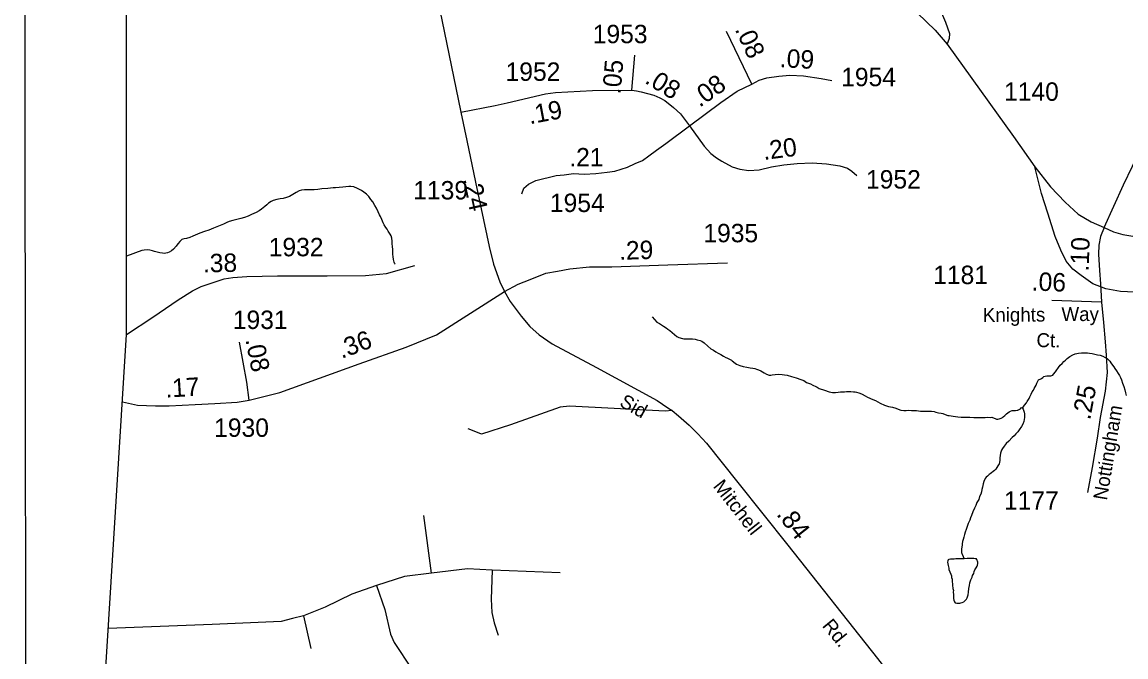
# Model space of a CAD drawing. Extents: x 2126262 to 2293712, y 749403 to 919119.
# Drawn here: x 2133630 to 2141122, y 833147 to 837456 of the extents above; entities that cross this region are included whole.
import ezdxf

# ---------------------------------------------------------------- set-up
doc = ezdxf.new("R2010")
doc.units = 0
for name, color, linetype in [('Exist Boundary Political CountyLine', 7, 'Continuous'), ('Exist Hydrographic Creek Single Shore', 7, 'Continuous'), ('Exist Hydrographic Misc Water Feature', 7, 'Continuous'), ('Exist Road Non-System Type 51', 7, 'Continuous'), ('Exist Road Secondary Mileage Hundredths English Label', 7, 'Continuous'), ('Exist Road Secondary Type 51 Attributed', 7, 'Continuous'), ('Exist Road Secondary Type 51 Label', 7, 'Continuous'), ('Exist Road Secondary Type 51 Number Label', 7, 'Continuous'), ('Map Preparation Inset Cut Line', 7, 'Continuous')]:
    doc.layers.add(name, color=color, linetype=linetype)

msp = doc.modelspace()

# ---------------------------------------------------------------- linework, layer by layer
at = {"layer": 'Exist Boundary Political CountyLine'}
msp.add_lwpolyline([(2133839.4, 827270.1), (2134339.4, 835334.3), (2134341.8, 841203.1), (2134508, 848637.7), (2140998.3, 864497.6)], dxfattribs=at)
at = {"layer": 'Exist Hydrographic Creek Single Shore'}
msp.add_lwpolyline([(2140527.4, 835028.2), (2140533.2, 835029.3), (2140539.3, 835032.5), (2140547.7, 835037.3), (2140557.6, 835044.7), (2140565.6, 835050), (2140573.1, 835052.5), (2140585.4, 835054.7), (2140599.2, 835055.1), (2140611.5, 835054.8), (2140619.9, 835057.2), (2140625.8, 835059.5), (2140631, 835065.3), (2140643.1, 835081.3), (2140648.6, 835089.4), (2140665, 835111.2), (2140676.1, 835126.6), (2140688.4, 835139.4), (2140700.7, 835151.7), (2140710.9, 835160.3), (2140723.9, 835171.7), (2140742.1, 835186), (2140760.4, 835197), (2140777.8, 835204.1), (2140799.5, 835209.4), (2140819.6, 835210.8), (2140843.8, 835210.8), (2140860.4, 835210.7), (2140875.6, 835209.6), (2140893.6, 835205.6), (2140910.5, 835202.3), (2140927.9, 835197.6), (2140946.1, 835194.1), (2140965.8, 835187.8), (2140982, 835180.1), (2140994.5, 835171.7), (2141004.2, 835162.6), (2141012.2, 835154.1), (2141020.4, 835142.6), (2141030.6, 835128.1), (2141038.6, 835116.7), (2141046.4, 835105.1), (2141056.9, 835089.2), (2141068.8, 835070.8), (2141077.8, 835056.1), (2141085.4, 835042.7), (2141091.1, 835026.8), (2141099.5, 835005.3), (2141107.7, 834983), (2141113.9, 834961), (2141120, 834939.3), (2141124.1, 834921.2)], dxfattribs=at)
at = {"layer": 'Exist Hydrographic Misc Water Feature'}
for points in [[(2136162.1, 835811.9), (2136160.2, 835815.8), (2136156.1, 835827.4), (2136151.8, 835844.3), (2136149.8, 835865.3), (2136147.5, 835879.4), (2136147.1, 835893.2), (2136145.5, 835913.8), (2136145, 835929.3), (2136142.8, 835953.2), (2136143, 835969.8), (2136140.7, 835989.6), (2136134.4, 836005.9), (2136128.2, 836017.4), (2136115.9, 836037.5), (2136108.1, 836049.3), (2136099.9, 836061.9), (2136088, 836079.1), (2136081.9, 836093), (2136075.7, 836104.9), (2136071.4, 836114.9), (2136063.4, 836135.5), (2136055.4, 836148.6), (2136047, 836166.9), (2136035.1, 836192.6), (2136024.5, 836210.9), (2136010.3, 836234.9), (2135998.4, 836252.5), (2135984.1, 836270.9), (2135968.1, 836288.3), (2135950, 836301.6), (2135933.4, 836311.8), (2135907.6, 836327.1), (2135881.6, 836337.5), (2135861.9, 836338.9), (2135847.9, 836339), (2135827.6, 836337.2), (2135807.7, 836335), (2135781.7, 836332.4), (2135758.1, 836330.3), (2135741.9, 836329.9), (2135705.8, 836325.6), (2135663.8, 836323.5), (2135638, 836318.9), (2135613.8, 836316.8), (2135555.9, 836316.7), (2135546.3, 836316.5), (2135527.6, 836314.5), (2135510.4, 836310.2), (2135489.9, 836299.9), (2135468.4, 836285.7), (2135444.4, 836271.1), (2135425.9, 836264.9), (2135402.3, 836258.8), (2135382.7, 836255.2), (2135358.5, 836250.8), (2135334.9, 836244.6), (2135320.7, 836238.6), (2135303.1, 836226.3), (2135290.6, 836216), (2135277.3, 836204.2), (2135255.5, 836185.6), (2135239.3, 836175.5), (2135219.4, 836163.5), (2135203.7, 836155.7), (2135187.9, 836149.2), (2135164.1, 836139), (2135140.1, 836130.5), (2135115.9, 836122.8), (2135087.8, 836115.3), (2135060.3, 836108.5), (2135036.1, 836101.6), (2135020.3, 836095.5), (2134996.6, 836085.3), (2134964.4, 836071.1), (2134930.7, 836057.1), (2134898.7, 836044.5), (2134868.6, 836033.6), (2134837.2, 836022.2), (2134789.2, 836001.8), (2134769.4, 835993.9), (2134747.4, 835987.9), (2134731.2, 835985), (2134721.2, 835983.3), (2134715.2, 835981), (2134709.5, 835974.5), (2134701.9, 835966.8), (2134689.8, 835952.8), (2134681.6, 835942.6), (2134676.1, 835934.2), (2134658.2, 835914.1), (2134643.9, 835902.1), (2134628.7, 835894.3), (2134616.4, 835890.5), (2134594.4, 835886.1), (2134584.4, 835886.4), (2134566.1, 835889.9), (2134547.9, 835894.4), (2134528.4, 835899.7), (2134514.5, 835903.4)], [(2134514.5, 835903.4), (2134498.1, 835906.8), (2134480.2, 835909), (2134458.1, 835906.7), (2134442.1, 835904.7), (2134339.6, 835867.6)], [(2137906.6, 835455.3), (2137938.8, 835419.2), (2137956.9, 835410), (2137969, 835401.6), (2137983.1, 835392.2), (2138001.2, 835380.1), (2138013.5, 835371.8), (2138025.4, 835362.7), (2138043.4, 835348.1), (2138057.6, 835336.3), (2138073.8, 835322.9), (2138087.9, 835314.6), (2138111.7, 835309), (2138122, 835307.1), (2138143.7, 835305), (2138165.8, 835305.3), (2138180, 835305.2), (2138198, 835304.1), (2138211.8, 835299.6), (2138231.7, 835294.1), (2138244.2, 835289.8), (2138260, 835278.1), (2138284.4, 835256.1), (2138304.5, 835238.5), (2138322.3, 835228.5), (2138338.5, 835216.7), (2138354.7, 835209), (2138372.7, 835199.3), (2138391, 835189.3), (2138406.8, 835179.2), (2138412.7, 835177.4), (2138445.1, 835162), (2138449, 835157.8), (2138469.1, 835140.1), (2138479.2, 835134.1), (2138501.3, 835124.7), (2138523.7, 835118.5), (2138549.1, 835113), (2138571.4, 835109.2), (2138589.3, 835107.3), (2138603.4, 835105.6), (2138615.5, 835100.9), (2138627.6, 835095), (2138643.8, 835089.7), (2138655.5, 835081.5), (2138667.4, 835076), (2138683.6, 835065.8), (2138699.6, 835059.8), (2138711.9, 835060.4), (2138722.1, 835062.1), (2138741.6, 835064.8), (2138763.6, 835066.7), (2138788, 835064.7), (2138805.8, 835062.8), (2138821.8, 835059.1), (2138851.9, 835050.9), (2138883.9, 835041.2), (2138915.9, 835029.9), (2138936.4, 835022.3), (2138953.9, 835010.3), (2138980.3, 835000.6), (2138996.3, 834992.1), (2139016.6, 834983), (2139026.6, 834977), (2139040.6, 834969.2), (2139076.7, 834956.9), (2139108.5, 834945.6), (2139130.8, 834941.8), (2139150.9, 834942.4), (2139169.2, 834944.5), (2139184.7, 834946.6), (2139198.7, 834946.1), (2139208.5, 834947), (2139212.8, 834946.8), (2139224.7, 834949.1), (2139242.4, 834948.8), (2139254.9, 834949.4), (2139272.7, 834947.1), (2139284.8, 834945.2), (2139292.6, 834943.6), (2139308.4, 834939.2), (2139326.6, 834933.6), (2139330.7, 834929.8), (2139352.9, 834919.9), (2139368.9, 834909.8), (2139405.2, 834894.6), (2139421.2, 834886.9), (2139455, 834870.4), (2139483.3, 834856.7), (2139511.6, 834847.2), (2139537.4, 834841.7), (2139559.4, 834835.5), (2139575.4, 834829.5), (2139593.6, 834821.8), (2139615.3, 834820.5), (2139631.5, 834820.1), (2139643.4, 834820.8), (2139665.6, 834820.2), (2139691.6, 834818.8), (2139699.6, 834818.8)], [(2140418.1, 834840.6), (2140423.3, 834843.2), (2140433.3, 834855), (2140447, 834871.2), (2140452.6, 834881.7), (2140464.7, 834901.3), (2140470.6, 834913.4), (2140478.4, 834929.7), (2140486.2, 834946), (2140494.2, 834958.1), (2140499.9, 834967.8), (2140511.8, 834992.4), (2140517.6, 835006.2), (2140521.7, 835014), (2140527.4, 835028.2)], [(2139699.6, 834818.8), (2139727.5, 834814.9), (2139753.6, 834815.1), (2139773.6, 834815.7), (2139789.8, 834816.1), (2139803.4, 834814), (2139819.6, 834811.9), (2139831.7, 834807.7), (2139849.3, 834804.2), (2139867.6, 834800.7), (2139879.9, 834798.4), (2139895.9, 834792.3), (2139913.9, 834786.3), (2139921.9, 834784.7), (2139949.6, 834780.9), (2139981.8, 834777.6), (2140004.1, 834773.9), (2140033.9, 834773.8), (2140062, 834774.1), (2140089.6, 834771.9), (2140122, 834772.3), (2140143.8, 834772.6), (2140155.7, 834773.2), (2140167.6, 834773.1), (2140183.8, 834773.5), (2140200, 834773.1), (2140211.8, 834773.7), (2140227.8, 834767.6), (2140234.4, 834765.8), (2140243.8, 834761.5), (2140251.8, 834761.1), (2140262.1, 834763.6), (2140274, 834768.4), (2140283.8, 834772.1), (2140289.6, 834776.1), (2140299.8, 834785.9), (2140311.5, 834797.9), (2140319.5, 834802.8), (2140329.3, 834810.7), (2140339.4, 834814.4), (2140349.4, 834818.6), (2140361.3, 834818.8), (2140373.2, 834818.7), (2140383.3, 834820.8), (2140387.4, 834822.5), (2140397.6, 834827.1), (2140405.4, 834831.2), (2140411.2, 834836.9), (2140418.1, 834840.6)], [(2140418.1, 834840.6), (2140425.1, 834829.1), (2140429.6, 834815), (2140431.3, 834807.8), (2140433.3, 834797), (2140433.5, 834785.6), (2140433.5, 834773), (2140431.9, 834759.4), (2140427.8, 834745.4), (2140422.6, 834727.6), (2140412.4, 834711.3), (2140398.2, 834688.7), (2140388.8, 834674.7), (2140374.5, 834660.6), (2140362.8, 834648.2), (2140349.2, 834636.5), (2140326.9, 834612.2), (2140309.7, 834594.6), (2140295.5, 834578.5), (2140283.8, 834562), (2140277.9, 834549.9), (2140269.9, 834529.6), (2140268, 834514), (2140266.2, 834497.7), (2140266.2, 834482.3), (2140264.5, 834467.5), (2140260.9, 834457.5), (2140253.1, 834443.7), (2140246.7, 834431.7), (2140239.1, 834421.1), (2140228.9, 834411.6), (2140221.1, 834405.1), (2140209.2, 834397.2), (2140201.2, 834390.7), (2140193.6, 834385.3), (2140181.3, 834375), (2140173.5, 834366.9), (2140167.6, 834357.2), (2140157.5, 834336.8), (2140153.4, 834322.8), (2140148.1, 834298.5), (2140144, 834284.5), (2140140.5, 834268.4), (2140136.2, 834252.8), (2140128.4, 834236.6), (2140122.9, 834216.3), (2140110.8, 834194.2), (2140103.2, 834174.6), (2140093.3, 834155.9), (2140083.9, 834132.5), (2140073.8, 834108.1), (2140067.7, 834091.9), (2140062.2, 834076.2), (2140052.1, 834053.3), (2140044.1, 834031.4), (2140036.5, 834011.9), (2140030.6, 833993.3), (2140026.7, 833977.7), (2140021.1, 833959.8), (2140017, 833945.1), (2140013.1, 833929.8), (2140009.7, 833915.8), (2140009.5, 833907.7), (2140007.6, 833891.3), (2140005.8, 833879.8), (2140005.6, 833869.3), (2140005.8, 833855.1), (2140007.8, 833849.5), (2140009.9, 833843.5), (2140023.6, 833813.8)], [(2140023.6, 833813.8), (2140014.2, 833813.2), (2140002.3, 833813.4), (2139992.6, 833813.6), (2139978.5, 833813), (2139968.2, 833813.3), (2139956.4, 833811), (2139944.5, 833810.4), (2139932.2, 833810.6), (2139920.3, 833808.8), (2139914.3, 833806), (2139912.3, 833799), (2139910.6, 833790.8), (2139912.7, 833778.3), (2139915.1, 833766.9), (2139918.8, 833750.6), (2139920.9, 833740.5), (2139927.2, 833724.5), (2139933.6, 833709), (2139937.3, 833696.6), (2139939.1, 833686.6), (2139943.6, 833675), (2139943.4, 833666.9), (2139945.9, 833634.9), (2139948.1, 833612.6), (2139950.6, 833597.3), (2139950.4, 833588.8), (2139950.6, 833569.3), (2139950.6, 833561.2), (2139952.7, 833551.1), (2139952.7, 833543), (2139954.3, 833533), (2139956.8, 833524.9), (2139958.6, 833520.6), (2139962.9, 833515.1), (2139975, 833511.2), (2139983, 833511.2), (2139995.3, 833511), (2140001.3, 833513.3), (2140010.7, 833517.1), (2140020.9, 833522.1), (2140028.9, 833527.4), (2140040.8, 833539.4), (2140044.7, 833547.7), (2140050.3, 833568), (2140052.3, 833585.9), (2140055.8, 833612.2), (2140060.1, 833631.8), (2140063.4, 833650), (2140069.3, 833670.2), (2140077.3, 833689.6), (2140081.6, 833700.4), (2140089.4, 833713.8), (2140092.9, 833727.8), (2140097, 833738.6), (2140104.8, 833750.8), (2140112.6, 833764.2), (2140114.4, 833770), (2140116.7, 833780.7), (2140116.1, 833790.5), (2140114.7, 833796.4), (2140112.6, 833802), (2140106.7, 833812.2), (2140098.5, 833813.8), (2140088.6, 833815.7), (2140080.4, 833815.7), (2140070.4, 833816.1), (2140056.6, 833815.7), (2140043.9, 833816), (2140023.6, 833813.8)]]:
    msp.add_lwpolyline(points, dxfattribs=at)
at = {"layer": 'Exist Road Non-System Type 51'}
for p, q in [((2136408.9, 833716.4), (2136358.1, 834107.8)), ((2137283.1, 833719), (2136820.6, 833736.8)), ((2135541.1, 833425.5), (2135589.4, 833204.4))]:
    msp.add_line(p, q, dxfattribs=at)
for points in [[(2139907.9, 837304.1), (2139924.5, 837346.3), (2139926.5, 837376), (2139899.7, 837452.8), (2139815.7, 837648.5), (2139756.4, 837775.8), (2139700.7, 837888.9), (2139659.9, 837947.7)], [(2142165.1, 835974.1), (2142032.1, 835926.8), (2141927.6, 835899), (2141869.2, 835882.2), (2141774.2, 835832.2), (2141493.3, 835689.9), (2141380.3, 835642.3), (2141315.9, 835625.6), (2141225.8, 835619.5), (2141084, 835626.4), (2140984.3, 835644.4), (2140897.1, 835680.2), (2140818.2, 835735.9), (2140761.1, 835779), (2140716.2, 835832), (2140679.8, 835908.7), (2140641.7, 835999.5), (2140591, 836158.6), (2140549.7, 836293.4), (2140503.4, 836472.4)], [(2137346.6, 834849.8), (2137283.1, 834842.2), (2136945.1, 834722.7), (2136749.4, 834659.2), (2136708.8, 834674.5), (2136657.9, 834694.8)], [(2138042.9, 834819.3), (2137994.6, 834814.2), (2137346.6, 834849.8)], [(2136408.9, 833716.4), (2136224.7, 833692.3), (2136036.6, 833631.3)], [(2136820.6, 833736.8), (2136652.8, 833744.4), (2136408.9, 833716.4)], [(2136820.6, 833736.8), (2136814.2, 833539.8), (2136819.3, 833448.4), (2136834.5, 833379.7), (2136862.5, 833295.9)], [(2136036.6, 833631.3), (2135868.9, 833572.9), (2135688.5, 833483.9), (2135541.1, 833425.5)], [(2136036.6, 833631.3), (2136092.5, 833468.7), (2136130.6, 833301), (2136156, 833245.1), (2136275.5, 833064.6)], [(2135541.1, 833425.5), (2135466.1, 833409), (2135389.9, 833388.6), (2134919.8, 833368.3), (2134215.7, 833340.4)]]:
    msp.add_lwpolyline(points, dxfattribs=at)
at = {"layer": 'Exist Road Secondary Type 51 Attributed'}
for p, q in [((2138583.7, 837035.4), (2138411.1, 837392.7)), ((2137767.8, 836993.1), (2137789.2, 837231.8)), ((2140956.5, 835554.3), (2140619, 835566.7))]:
    msp.add_line(p, q, dxfattribs=at)
for points in [[(2136268.5, 840081.4), (2136362.6, 840057.4), (2136501.7, 840007.2), (2136664, 839926), (2136940.2, 839797.1), (2137462.7, 839535.1), (2137674.5, 839428.7), (2137977.4, 839180.4), (2138132.6, 839043.2), (2138330.6, 838849.2), (2138544.5, 838652.7), (2138838.4, 838356.7), (2139013, 838191.1), (2139320.7, 837893.9), (2139707, 837516.6), (2139826.8, 837400.7), (2139907.5, 837304.7), (2140358, 836679.5), (2140503.4, 836472.4), (2140610.7, 836338.1), (2140708.5, 836234.1), (2140798.2, 836151.3), (2140885.4, 836100.6), (2140973.7, 836060.8)], [(2135544.8, 840069.7), (2135724.2, 839700.8), (2135847.7, 839451.3), (2135954.5, 839229.9), (2136026.3, 839085.6), (2136110.3, 838910.1), (2136175.7, 838774.2), (2136207.6, 838693.8), (2136228.6, 838625.5), (2136249.4, 838551.5), (2136286.7, 838393.2), (2136342.6, 838131.6), (2136395.2, 837878.8), (2136511.7, 837316), (2136608.7, 836845)], [(2138583.7, 837035.4), (2138633.5, 837060.7), (2138685.3, 837076.2), (2138765.9, 837089.4), (2138839.8, 837094.9), (2138932.5, 837091.6), (2139053.9, 837072.9), (2139126.8, 837058.5)], [(2138160.7, 836751), (2138371.9, 836910.6), (2138483.4, 836985.7), (2138583.7, 837035.4)], [(2136608.7, 836845), (2136840.1, 836890.6), (2136923.2, 836907.5), (2137182.2, 836968), (2137249.5, 836976.8), (2137334.5, 836981.3), (2137501.2, 836992.3), (2137767.8, 836993.1)], [(2137767.8, 836993.1), (2137799.3, 836988.6), (2137833, 836981.9), (2137918.3, 836959.2), (2137958.1, 836941.5), (2137993.4, 836922.8), (2138050.8, 836875.3), (2138099.3, 836832.3), (2138160.7, 836751)], [(2136608.7, 836845), (2136648.6, 836651.6), (2136707.6, 836368.9), (2136800.1, 835931.8), (2136828.8, 835811.8), (2136871.9, 835692.4), (2136903.8, 835626.1)], [(2137022.2, 836290.4), (2137036.5, 836329), (2137067.4, 836356.6), (2137118.2, 836380.9), (2137255, 836414), (2137309.1, 836419.5), (2137373.1, 836427.2), (2137446, 836423.9), (2137524.3, 836427.2), (2137600.5, 836436.1), (2137652.3, 836443.8), (2137738.4, 836471.4), (2137791.4, 836496.8), (2137840, 836516.6), (2137885, 836548.2), (2137935.6, 836585.4), (2137999.4, 836630.6), (2138160.7, 836751)], [(2138160.7, 836751), (2138259.3, 836612.7), (2138305.7, 836564.1), (2138344.3, 836534.3), (2138378.9, 836511.4), (2138450.3, 836473.6), (2138502.1, 836458.1), (2138562.8, 836449.3), (2138632.4, 836452.6), (2138716.2, 836472.5), (2138799.6, 836486.8), (2138890.6, 836496.8), (2138992.1, 836500.1), (2139089.3, 836493.5), (2139180.9, 836479.1), (2139232.7, 836463.7), (2139262.5, 836444.9), (2139295.6, 836415.1)], [(2140973.7, 836060.8), (2141106.1, 836352.2), (2141227.5, 836603.8)], [(2140973.7, 836060.8), (2141037.7, 836033.2), (2141100.6, 836014.5), (2141169.7, 836002.6), (2141333.3, 835983.2), (2141737.3, 835980.9), (2141961, 835970.3), (2142669.1, 835973.7), (2142757.3, 835981.9), (2142823.8, 835987.2), (2142945.6, 836010.5), (2143099.3, 836052.8), (2143517.2, 836193.6), (2143885.3, 836274.6), (2144423.3, 836277.5), (2145107.1, 836267.4)], [(2140973.7, 836060.8), (2140949.4, 836000.1), (2140937.3, 835941.6), (2140935.1, 835879.6), (2140942.6, 835769.6), (2140950.2, 835680), (2140956.5, 835554.3)], [(2134339.4, 835335.5), (2134518.7, 835452.5), (2134690.1, 835571.4), (2134786.5, 835631.5), (2134845.4, 835661), (2135002.8, 835713.3), (2135060.2, 835722.6), (2135155.7, 835728.5), (2135365, 835732.5), (2135699.9, 835733.8), (2135960.7, 835736.5), (2136104.7, 835748.4), (2136294.9, 835803.8)], [(2136903.8, 835626.1), (2136996.9, 835677), (2137078.2, 835708.7), (2137185.8, 835752.3), (2137263.3, 835766.1), (2137348.3, 835781.2), (2137481.8, 835793.9), (2137633.6, 835794.7), (2138013, 835807.4), (2138417.5, 835821.7)], [(2135172.7, 834888.7), (2135379.5, 834942.6), (2135918.5, 835136.8), (2136237.9, 835249.6), (2136443, 835334.2), (2136903.8, 835626.1)], [(2136903.8, 835626.1), (2136942.1, 835559.1), (2137017.1, 835458.9), (2137076.5, 835390.6), (2137139.6, 835333.1), (2137227.4, 835272.5), (2137527.7, 835111.1), (2137939.6, 834887.7), (2138013, 834838.6), (2138042.9, 834819.3), (2138086.4, 834784.3), (2138157.5, 834720.5), (2138215.6, 834661.1), (2138274.6, 834597.3), (2138488.1, 834329.9), (2138827.6, 833906.2), (2139435.5, 833136.5), (2139499.9, 833055.5), (2139642.9, 832848.1), (2139685, 832761.9), (2139723.6, 832675.8), (2139768.9, 832556.4), (2139791.3, 832487.5)], [(2140956.5, 835554.3), (2140968.9, 835417.9), (2140979.9, 835285.6), (2140988.1, 835196), (2140993.7, 835077.4), (2140979.9, 834950.6), (2140946.1, 834772.8), (2140925.5, 834632.2), (2140891.7, 834433.7), (2140860, 834264.2)], [(2135172.7, 834888.7), (2135154.8, 835011.2), (2135106.4, 835283.8)], [(2134311.1, 834878.7), (2134412.7, 834856.8), (2134535.5, 834851.5), (2134628.2, 834850.2), (2134804.3, 834860.9), (2134937.8, 834866.3), (2135090, 834876.9), (2135172.7, 834888.7)]]:
    msp.add_lwpolyline(points, dxfattribs=at)
at = {"layer": 'Map Preparation Inset Cut Line'}
msp.add_lwpolyline([(2133630.5, 852884.6), (2189691.2, 852884.6), (2189691.2, 811054.9), (2164878.1, 811054.9), (2133665.4, 826054.8)], close=True, dxfattribs=at)

# ---------------------------------------------------------------- texts
at = {"layer": 'Exist Road Secondary Mileage Hundredths English Label'}
for s, rotation, p in [('.08', 294.94344, (2138465.9, 837406.9)), ('.09', 356.63506, (2138770.1, 837150.7)), ('.05', 85.10986, (2137691.9, 836963.5)), ('.08', 328.48122, (2137849.9, 837046.1)), ('.08', 35.10593, (2138228.7, 836873.4)), ('.19', 10.64111, (2137076.2, 836761.8)), ('.20', 7.34814, (2138664.5, 836519.5)), ('.24', 282.56819, (2136620.1, 836390.2)), ('.29', 1.69011, (2137683.6, 835841.9)), ('.10', 88.00756, (2140868.5, 835762)), ('.38', 1.08049, (2134858.7, 835756.6)), ('.06', 357.8947, (2140480.8, 835634.4)), ('.36', 20.54836, (2135798.9, 835169.7)), ('.08', 281.18621, (2135146.1, 835300.3)), ('.17', 3.46668, (2134606.1, 834906.7)), ('.25', 79.25379, (2140878.4, 834751.2)), ('.84', 308.14842, (2138745.9, 834114))]:
    msp.add_text(s, height=125, rotation=rotation, dxfattribs=at).set_placement(p)
msp.add_text('.21', height=125, dxfattribs=at).set_placement((2137343.9, 836476.2))
at = {"layer": 'Exist Road Secondary Type 51 Label'}
for s, rotation, p in [('Knights', 0.35636, (2140151, 835420.7)), ('Way', 0.35636, (2140684.7, 835425.8)), ('Ct.', 358.85465, (2140514, 835250.4)), ('Sid', 330.7165, (2137678.2, 834853.2)), ('Nottingham', 80.59537, (2140992.5, 834206.3)), ('Mitchell', 308.25232, (2138315.2, 834303.9)), ('Rd.', 309.15895, (2139056, 833357.3))]:
    msp.add_text(s, height=95, rotation=rotation, dxfattribs=at).set_placement(p)
at = {"layer": 'Exist Road Secondary Type 51 Number Label'}
for s, p in [('1953', (2137503.4, 837312.2)), ('1952', (2136911.8, 837056.8)), ('1954', (2139189.2, 837020.5)), ('1140', (2140294.7, 836921.5)), ('1952', (2139357.8, 836325.9)), ('1139', (2136285.2, 836251.8)), ('1954', (2137212.6, 836166.6)), ('1935', (2138254, 835961.3)), ('1932', (2135304.3, 835866.2)), ('1181', (2139813.8, 835677.5)), ('1931', (2135060.6, 835372.8)), ('1930', (2134933.8, 834640.9)), ('1177', (2140294.1, 834146.6))]:
    msp.add_text(s, height=125, dxfattribs=at).set_placement(p)

doc.saveas('drawing.dxf')
